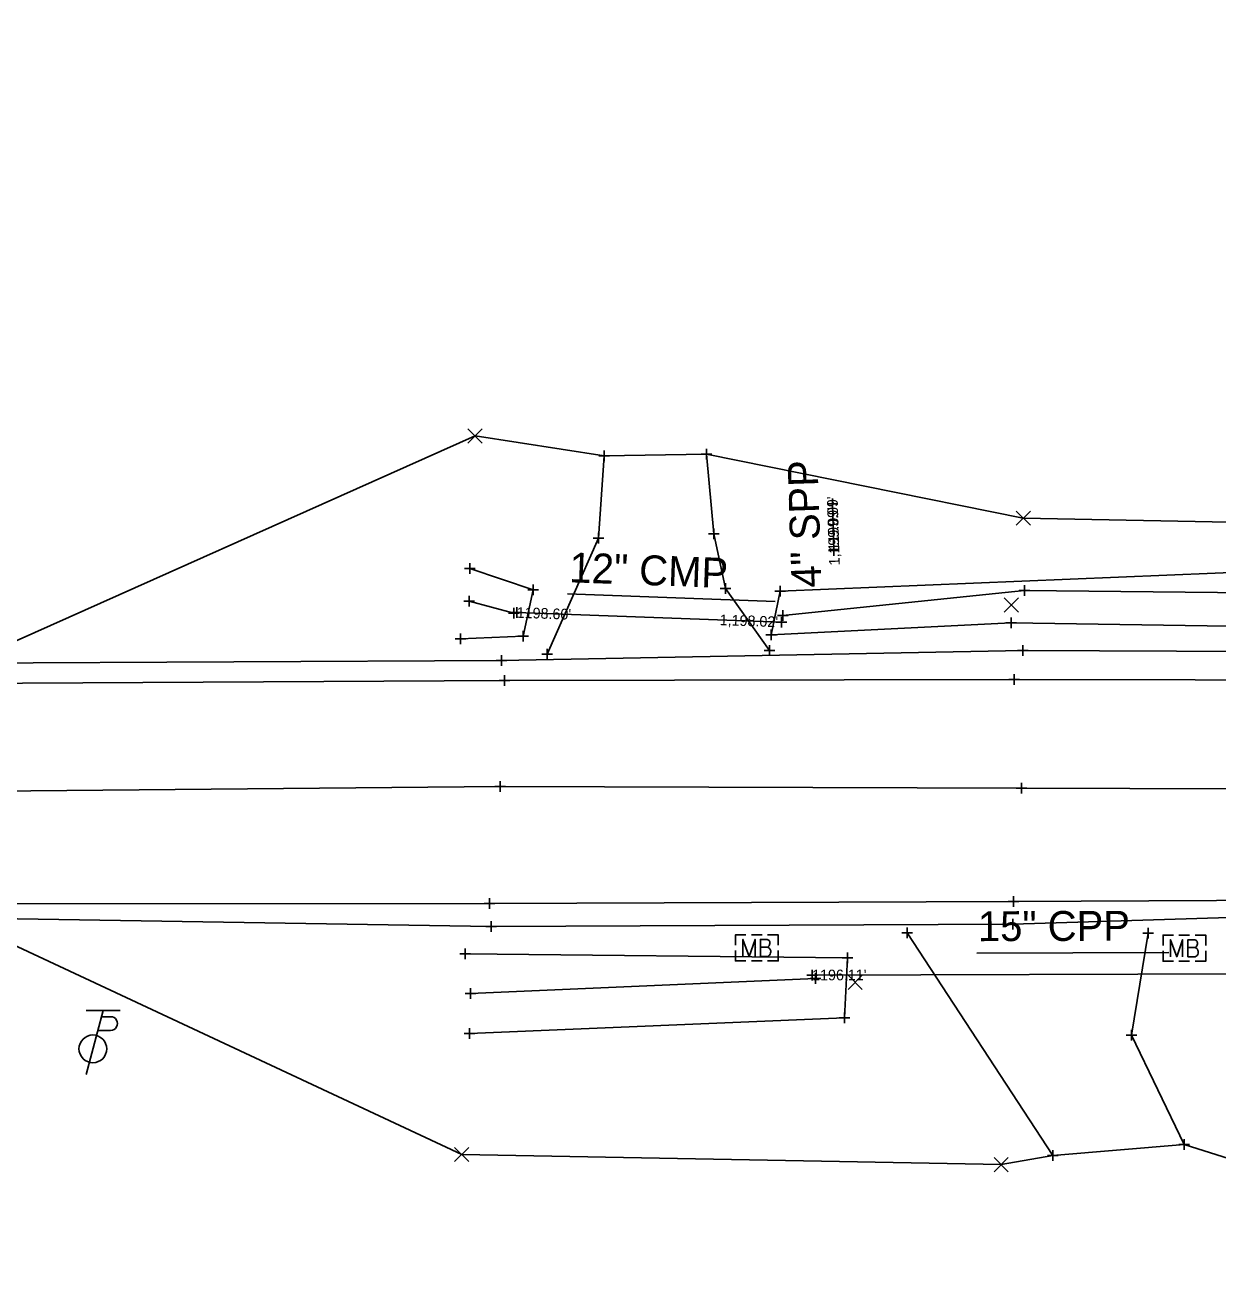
# Model space of a CAD drawing. Extents: x 2319153 to 2321514, y 575338 to 575500.
# Drawn here: x 2320371.3 to 2320483, y 575366.1 to 575483.2 of the extents above; entities that cross this region are included whole.
import ezdxf

# ---------------------------------------------------------------- set-up
doc = ezdxf.new("R2010")
doc.units = 0
for name, color, linetype in [('Default', 7, 'Continuous'), ('DR_X_Ditch', 7, 'Continuous'), ('DR_X_Elev_Flow', 7, 'Continuous'), ('DR_X_Storm_Sewer', 7, 'Continuous'), ('DR_X_Text', 7, 'Continuous'), ('PV_X_COP', 7, 'Continuous'), ('PV_X_Driveway', 7, 'Continuous'), ('PV_X_EOP', 7, 'Continuous'), ('PV_X_Shoulder', 7, 'Continuous'), ('RD_X_Cells', 7, 'Continuous'), ('SC_Scratch1', 7, 'Continuous'), ('SV_X_Break_Lines', 7, 'Continuous'), ('SV_X_Random_Point', 7, 'Continuous'), ('SV_X_Shot_Marker', 7, 'Continuous'), ('SV_X_Terrain_Boundary', 7, 'Continuous'), ('UT_X_Misc_Cells', 7, 'Continuous')]:
    doc.layers.add(name, color=color, linetype=linetype)

msp = doc.modelspace()

# ---------------------------------------------------------------- linework, layer by layer
at = {"layer": 'Default'}
msp.add_line((2320447.05, 575434.03), (2320447.05, 575434.03), dxfattribs=at)
at = {"layer": 'DR_X_Ditch'}
for points in [[(2320442.27, 575427.97), (2320464.89, 575430.3), (2320567.27, 575429.23), (2320616.67, 575430.56), (2320664.25, 575431.29), (2320715.69, 575433.03), (2320722.62, 575480.62)], [(2320417.08, 575428.19), (2320412.9, 575429.31)], [(2320445.33, 575393.97), (2320413.01, 575392.58)]]:
    msp.add_lwpolyline(points, dxfattribs=at)
at = {"layer": 'DR_X_Elev_Flow'}
for p, q in [((2320446.91, 575438.92), (2320446.91, 575437.92)), ((2320446.41, 575438.42), (2320447.41, 575438.42)), ((2320446.91, 575438.42), (2320446.91, 575438.42)), ((2320446.55, 575434.03), (2320447.55, 575434.03)), ((2320447.05, 575434.53), (2320447.05, 575433.53)), ((2320447.05, 575434.03), (2320447.05, 575434.03)), ((2320416.85, 575428.25), (2320417.85, 575428.25)), ((2320417.35, 575428.75), (2320417.35, 575427.75)), ((2320417.35, 575428.25), (2320417.35, 575428.25)), ((2320441.64, 575427.35), (2320442.64, 575427.35)), ((2320442.14, 575427.85), (2320442.14, 575426.85)), ((2320442.14, 575427.35), (2320442.14, 575427.35)), ((2320444.51, 575394.3), (2320445.51, 575394.3)), ((2320445.01, 575394.8), (2320445.01, 575393.8)), ((2320445.01, 575394.3), (2320445.01, 575394.3))]:
    msp.add_line(p, q, dxfattribs=at)
at = {"layer": 'DR_X_Storm_Sewer'}
for p, q in [((2320447.05, 575434.03), (2320446.91, 575438.42)), ((2320417.35, 575428.25), (2320442.14, 575427.35)), ((2320445.01, 575394.3), (2320489.84, 575394.42))]:
    msp.add_line(p, q, dxfattribs=at)
at = {"layer": 'DR_X_Text'}
for p, q in [((2320441.54, 575429.27), (2320422.09, 575429.98)), ((2320478.41, 575396.42), (2320460.43, 575396.36))]:
    msp.add_line(p, q, dxfattribs=at)
at = {"layer": 'PV_X_COP'}
msp.add_lwpolyline([(2320114.93, 575411.33), (2320165.7, 575411.06), (2320216.04, 575411.34), (2320265.84, 575411.19), (2320315.14, 575411.25), (2320365.04, 575411.47), (2320415.78, 575411.96), (2320464.61, 575411.79), (2320515.32, 575411.65), (2320564.75, 575412.16), (2320614.38, 575411.69), (2320664.58, 575411.98), (2320714.9, 575412.38)], dxfattribs=at)
at = {"layer": 'PV_X_Driveway'}
for points in [[(2320425.54, 575442.92), (2320425, 575435.21), (2320420.2, 575424.33)], [(2320441.02, 575424.67), (2320436.9, 575430.5), (2320435.81, 575435.6), (2320435.13, 575443.06)], [(2320467.54, 575377.42), (2320453.9, 575398.24)], [(2320476.49, 575398.21), (2320474.92, 575388.68), (2320479.84, 575378.43)]]:
    msp.add_lwpolyline(points, dxfattribs=at)
at = {"layer": 'PV_X_EOP'}
for points in [[(2320093.83, 575421.33), (2320165.53, 575421.34), (2320217.08, 575420.91), (2320266.56, 575421.33), (2320315.91, 575421.64), (2320365.38, 575421.59), (2320416.21, 575421.87), (2320463.92, 575421.98), (2320514.77, 575421.86), (2320565.11, 575422.28), (2320615.12, 575422), (2320664.7, 575422.48), (2320715.11, 575422.41)], [(2320714.4, 575401.87), (2320664.35, 575401.67), (2320614.5, 575401.81), (2320564.7, 575401.89), (2320514.59, 575401.42), (2320463.88, 575401.2), (2320414.8, 575400.99), (2320364.6, 575400.96), (2320315.2, 575400.77), (2320265.49, 575400.71), (2320215.68, 575400.77), (2320165.34, 575400.63), (2320115.4, 575400.66)]]:
    msp.add_lwpolyline(points, dxfattribs=at)
at = {"layer": 'PV_X_Shoulder'}
for points in [[(2320077.57, 575423.62), (2320166.34, 575422.88), (2320218.2, 575423.13), (2320266.92, 575423.62), (2320316.5, 575423.54), (2320365.74, 575423.49), (2320415.91, 575423.76), (2320464.74, 575424.68), (2320515.05, 575424.47), (2320565.23, 575424.51), (2320615.54, 575424.46), (2320664.52, 575424.33), (2320715.19, 575424.71)], [(2320714.58, 575400.4), (2320664.56, 575400.05), (2320614.84, 575400.09), (2320564.64, 575399.89), (2320515.49, 575400.65), (2320463.79, 575399.05), (2320414.96, 575398.83), (2320364.78, 575399.66), (2320315.61, 575399.52), (2320265.3, 575399.56), (2320215.74, 575399.78), (2320165.72, 575399.22), (2320115.8, 575398.99)]]:
    msp.add_lwpolyline(points, dxfattribs=at)
at = {"layer": 'RD_X_Cells'}
for p, q in [((2320439.32, 575398.06), (2320440.32, 575398.06)), ((2320479.36, 575398.04), (2320480.36, 575398.04)), ((2320439.83, 575396.84), (2320439.83, 575396.84)), ((2320479.87, 575396.81), (2320479.87, 575396.81)), ((2320439.32, 575395.62), (2320440.32, 575395.62)), ((2320479.36, 575395.59), (2320480.36, 575395.59))]:
    msp.add_line(p, q, dxfattribs=at)
for points in [[(2320437.83, 575397.09), (2320437.83, 575398.06), (2320438.8, 575398.06)], [(2320438.53, 575396.04), (2320438.53, 575397.64), (2320439.11, 575396.04), (2320439.67, 575397.64), (2320439.67, 575396.04)], [(2320440.85, 575396.91), (2320440.92, 575396.98), (2320440.95, 575397.01), (2320440.98, 575397.05), (2320440.99, 575397.08), (2320441.02, 575397.13), (2320441.03, 575397.16), (2320441.05, 575397.25), (2320441.05, 575397.29), (2320441.05, 575397.34), (2320441.04, 575397.42), (2320441.02, 575397.48), (2320440.98, 575397.53), (2320440.92, 575397.58), (2320440.87, 575397.61), (2320440.84, 575397.62), (2320440.78, 575397.64), (2320440.16, 575397.64), (2320440.16, 575396.04), (2320440.85, 575396.04), (2320440.94, 575396.09), (2320441.02, 575396.16), (2320441.08, 575396.26), (2320441.12, 575396.37), (2320441.13, 575396.48), (2320441.13, 575396.56), (2320441.1, 575396.64), (2320441.05, 575396.75), (2320440.99, 575396.82), (2320440.85, 575396.91), (2320440.16, 575396.91)], [(2320440.84, 575398.06), (2320441.83, 575398.06), (2320441.83, 575397.09)], [(2320477.87, 575397.07), (2320477.87, 575398.04), (2320478.84, 575398.04)], [(2320478.57, 575396.01), (2320478.57, 575397.61), (2320479.15, 575396.01), (2320479.71, 575397.61), (2320479.71, 575396.01)], [(2320480.89, 575396.88), (2320480.96, 575396.95), (2320480.99, 575396.98), (2320481.02, 575397.02), (2320481.03, 575397.05), (2320481.06, 575397.1), (2320481.07, 575397.14), (2320481.09, 575397.22), (2320481.09, 575397.26), (2320481.09, 575397.31), (2320481.08, 575397.39), (2320481.06, 575397.45), (2320481.02, 575397.5), (2320480.96, 575397.55), (2320480.91, 575397.58), (2320480.88, 575397.59), (2320480.82, 575397.61), (2320480.2, 575397.61), (2320480.2, 575396.01), (2320480.89, 575396.01), (2320480.98, 575396.06), (2320481.06, 575396.13), (2320481.12, 575396.23), (2320481.16, 575396.34), (2320481.17, 575396.45), (2320481.17, 575396.53), (2320481.14, 575396.61), (2320481.09, 575396.72), (2320481.03, 575396.79), (2320480.89, 575396.88), (2320480.2, 575396.88)], [(2320480.88, 575398.04), (2320481.87, 575398.04), (2320481.87, 575397.07)], [(2320438.8, 575395.62), (2320437.83, 575395.62), (2320437.83, 575396.59)], [(2320441.83, 575396.59), (2320441.83, 575395.62), (2320440.84, 575395.62)], [(2320478.84, 575395.59), (2320477.87, 575395.59), (2320477.87, 575396.56)], [(2320481.87, 575396.56), (2320481.87, 575395.59), (2320480.88, 575395.59)]]:
    msp.add_lwpolyline(points, dxfattribs=at)
at = {"layer": 'SV_X_Break_Lines'}
for points in [[(2320732.93, 575442.06), (2320727.34, 575431.55), (2320720.41, 575425.89), (2320664.7, 575425.9), (2320613.83, 575426.05), (2320563.12, 575426.93), (2320514.6, 575426.5), (2320463.64, 575427.26), (2320441.18, 575426.16), (2320442.02, 575430.24), (2320514.44, 575433.22), (2320564.58, 575433.19), (2320614.81, 575433.37), (2320685.2, 575436.83)], [(2320412.95, 575432.36), (2320418.87, 575430.36), (2320417.96, 575426.01), (2320412.07, 575425.78)], [(2320412.92, 575388.84), (2320448.04, 575390.29), (2320448.32, 575395.92), (2320412.51, 575396.28)]]:
    msp.add_lwpolyline(points, dxfattribs=at)
at = {"layer": 'SV_X_Random_Point'}
for p, q in [((2320412.78, 575444.1), (2320414.11, 575445.44)), ((2320412.78, 575445.44), (2320414.11, 575444.1)), ((2320464.11, 575436.41), (2320465.45, 575437.74)), ((2320464.11, 575437.74), (2320465.45, 575436.41)), ((2320463, 575428.27), (2320464.34, 575429.6)), ((2320463, 575429.6), (2320464.34, 575428.27)), ((2320448.37, 575392.95), (2320449.71, 575394.29)), ((2320448.37, 575394.29), (2320449.71, 575392.95)), ((2320411.52, 575376.83), (2320412.86, 575378.16)), ((2320411.52, 575378.16), (2320412.86, 575376.83)), ((2320462.05, 575375.88), (2320463.38, 575377.21)), ((2320462.05, 575377.21), (2320463.38, 575375.88))]:
    msp.add_line(p, q, dxfattribs=at)
at = {"layer": 'SV_X_Shot_Marker'}
for p, q in [((2320425.54, 575443.42), (2320425.54, 575442.42)), ((2320435.13, 575443.56), (2320435.13, 575442.56)), ((2320425.04, 575442.92), (2320426.04, 575442.92)), ((2320425.54, 575442.92), (2320425.54, 575442.92)), ((2320434.63, 575443.06), (2320435.63, 575443.06)), ((2320435.13, 575443.06), (2320435.13, 575443.06)), ((2320424.5, 575435.21), (2320425.5, 575435.21)), ((2320425, 575435.71), (2320425, 575434.71)), ((2320425, 575435.21), (2320425, 575435.21)), ((2320435.31, 575435.6), (2320436.31, 575435.6)), ((2320435.81, 575436.1), (2320435.81, 575435.1)), ((2320435.81, 575435.6), (2320435.81, 575435.6)), ((2320412.95, 575432.86), (2320412.95, 575431.86)), ((2320412.45, 575432.36), (2320413.45, 575432.36)), ((2320412.95, 575432.36), (2320412.95, 575432.36)), ((2320418.37, 575430.36), (2320419.37, 575430.36)), ((2320418.87, 575430.86), (2320418.87, 575429.86)), ((2320418.87, 575430.36), (2320418.87, 575430.36)), ((2320436.4, 575430.5), (2320437.4, 575430.5)), ((2320436.9, 575431), (2320436.9, 575430)), ((2320436.9, 575430.5), (2320436.9, 575430.5)), ((2320442.02, 575430.74), (2320442.02, 575429.74)), ((2320464.89, 575430.8), (2320464.89, 575429.8)), ((2320412.4, 575429.31), (2320413.4, 575429.31)), ((2320412.9, 575429.81), (2320412.9, 575428.81)), ((2320412.9, 575429.31), (2320412.9, 575429.31)), ((2320441.52, 575430.24), (2320442.52, 575430.24)), ((2320442.02, 575430.24), (2320442.02, 575430.24)), ((2320464.39, 575430.3), (2320465.39, 575430.3)), ((2320464.89, 575430.3), (2320464.89, 575430.3)), ((2320416.58, 575428.19), (2320417.58, 575428.19)), ((2320417.08, 575428.69), (2320417.08, 575427.69)), ((2320417.08, 575428.19), (2320417.08, 575428.19)), ((2320442.27, 575428.47), (2320442.27, 575427.47)), ((2320441.77, 575427.97), (2320442.77, 575427.97)), ((2320442.27, 575427.97), (2320442.27, 575427.97)), ((2320463.14, 575427.26), (2320464.14, 575427.26)), ((2320463.64, 575427.76), (2320463.64, 575426.76)), ((2320463.64, 575427.26), (2320463.64, 575427.26)), ((2320411.57, 575425.78), (2320412.57, 575425.78)), ((2320412.07, 575426.28), (2320412.07, 575425.28)), ((2320412.07, 575425.78), (2320412.07, 575425.78)), ((2320417.46, 575426.01), (2320418.46, 575426.01)), ((2320417.96, 575426.51), (2320417.96, 575425.51)), ((2320417.96, 575426.01), (2320417.96, 575426.01)), ((2320440.68, 575426.16), (2320441.68, 575426.16)), ((2320441.18, 575426.66), (2320441.18, 575425.66)), ((2320441.18, 575426.16), (2320441.18, 575426.16)), ((2320420.2, 575424.83), (2320420.2, 575423.83)), ((2320440.52, 575424.67), (2320441.52, 575424.67)), ((2320441.02, 575425.17), (2320441.02, 575424.17)), ((2320441.02, 575424.67), (2320441.02, 575424.67)), ((2320464.24, 575424.68), (2320465.24, 575424.68)), ((2320464.74, 575425.18), (2320464.74, 575424.18)), ((2320464.74, 575424.68), (2320464.74, 575424.68)), ((2320415.41, 575423.76), (2320416.41, 575423.76)), ((2320415.91, 575424.26), (2320415.91, 575423.26)), ((2320415.91, 575423.76), (2320415.91, 575423.76)), ((2320419.7, 575424.33), (2320420.7, 575424.33)), ((2320420.2, 575424.33), (2320420.2, 575424.33)), ((2320416.21, 575422.37), (2320416.21, 575421.37)), ((2320463.92, 575422.48), (2320463.92, 575421.48)), ((2320415.71, 575421.87), (2320416.71, 575421.87)), ((2320416.21, 575421.87), (2320416.21, 575421.87)), ((2320463.42, 575421.98), (2320464.42, 575421.98)), ((2320463.92, 575421.98), (2320463.92, 575421.98)), ((2320415.28, 575411.96), (2320416.28, 575411.96)), ((2320415.78, 575412.46), (2320415.78, 575411.46)), ((2320415.78, 575411.96), (2320415.78, 575411.96)), ((2320464.11, 575411.79), (2320465.11, 575411.79)), ((2320464.61, 575412.29), (2320464.61, 575411.29)), ((2320464.61, 575411.79), (2320464.61, 575411.79)), ((2320414.8, 575401.49), (2320414.8, 575400.49)), ((2320463.38, 575401.2), (2320464.38, 575401.2)), ((2320463.88, 575401.7), (2320463.88, 575400.7)), ((2320463.88, 575401.2), (2320463.88, 575401.2)), ((2320414.3, 575400.99), (2320415.3, 575400.99)), ((2320414.8, 575400.99), (2320414.8, 575400.99)), ((2320414.46, 575398.83), (2320415.46, 575398.83)), ((2320414.96, 575399.33), (2320414.96, 575398.33)), ((2320414.96, 575398.83), (2320414.96, 575398.83)), ((2320453.9, 575398.74), (2320453.9, 575397.74)), ((2320463.29, 575399.05), (2320464.29, 575399.05)), ((2320463.79, 575399.55), (2320463.79, 575398.55)), ((2320463.79, 575399.05), (2320463.79, 575399.05)), ((2320453.4, 575398.24), (2320454.4, 575398.24)), ((2320453.9, 575398.24), (2320453.9, 575398.24)), ((2320475.99, 575398.21), (2320476.99, 575398.21)), ((2320476.49, 575398.71), (2320476.49, 575397.71)), ((2320476.49, 575398.21), (2320476.49, 575398.21)), ((2320412.51, 575396.78), (2320412.51, 575395.78)), ((2320448.32, 575396.42), (2320448.32, 575395.42)), ((2320412.01, 575396.28), (2320413.01, 575396.28)), ((2320412.51, 575396.28), (2320412.51, 575396.28)), ((2320447.82, 575395.92), (2320448.82, 575395.92)), ((2320448.32, 575395.92), (2320448.32, 575395.92)), ((2320445.33, 575394.47), (2320445.33, 575393.47)), ((2320413.01, 575393.08), (2320413.01, 575392.08)), ((2320444.83, 575393.97), (2320445.83, 575393.97)), ((2320445.33, 575393.97), (2320445.33, 575393.97)), ((2320412.51, 575392.58), (2320413.51, 575392.58)), ((2320413.01, 575392.58), (2320413.01, 575392.58)), ((2320448.04, 575390.79), (2320448.04, 575389.79)), ((2320447.54, 575390.29), (2320448.54, 575390.29)), ((2320448.04, 575390.29), (2320448.04, 575390.29)), ((2320412.42, 575388.84), (2320413.42, 575388.84)), ((2320412.92, 575389.34), (2320412.92, 575388.34)), ((2320412.92, 575388.84), (2320412.92, 575388.84)), ((2320474.42, 575388.68), (2320475.42, 575388.68)), ((2320474.92, 575389.18), (2320474.92, 575388.18)), ((2320474.92, 575388.68), (2320474.92, 575388.68)), ((2320479.84, 575378.93), (2320479.84, 575377.93)), ((2320467.54, 575377.92), (2320467.54, 575376.92)), ((2320479.34, 575378.43), (2320480.34, 575378.43)), ((2320479.84, 575378.43), (2320479.84, 575378.43)), ((2320467.04, 575377.42), (2320468.04, 575377.42)), ((2320467.54, 575377.42), (2320467.54, 575377.42))]:
    msp.add_line(p, q, dxfattribs=at)
at = {"layer": 'SV_X_Terrain_Boundary'}
for points in [[(2320707.74, 575483.24), (2320663.9, 575465.47), (2320613.22, 575460.31), (2320572.01, 575459.01), (2320513.06, 575436.13), (2320464.78, 575437.07), (2320435.13, 575443.06), (2320425.54, 575442.92), (2320413.45, 575444.77), (2320365.74, 575423.49), (2320316.5, 575423.54), (2320266.92, 575423.62), (2320218.2, 575423.13), (2320166.34, 575422.88), (2320077.57, 575423.62)], [(2320077.57, 575423.62), (2320093.83, 575421.33), (2320114.93, 575411.33), (2320115.4, 575400.66), (2320115.8, 575398.99), (2320165.72, 575399.22), (2320215.74, 575399.78), (2320265.3, 575399.56), (2320315.61, 575399.52), (2320364.78, 575399.66), (2320412.19, 575377.5), (2320462.72, 575376.55), (2320467.54, 575377.42), (2320479.84, 575378.43), (2320488.25, 575375.78), (2320513.78, 575375.33), (2320556.07, 575376.66), (2320613.57, 575378.25), (2320654.2, 575376.01), (2320714.52, 575366.13)]]:
    msp.add_lwpolyline(points, dxfattribs=at)
at = {"layer": 'UT_X_Misc_Cells'}
for p, q in [((2320380.21, 575390.99), (2320377.01, 575390.99)), ((2320378.61, 575390.99), (2320377.01, 575384.99)), ((2320378.45, 575390.39), (2320379.3, 575390.39)), ((2320378.11, 575389.12), (2320379.3, 575389.12))]:
    msp.add_line(p, q, dxfattribs=at)
msp.add_circle((2320377.65, 575387.39), 1.3, dxfattribs=at)
msp.add_arc((2320379.32, 575389.76), 0.638, 268.8767, 91.1233, dxfattribs=at)

# ---------------------------------------------------------------- texts
at = {"layer": 'DR_X_Text'}
for s, rotation, p in [('4" SPP', 91.8276, (2320445.89, 575430.61)), ('12" CMP', 357.9216, (2320422.24, 575431.07)), ('15" CPP', 0.1614, (2320460.54, 575397.47))]:
    msp.add_text(s, height=2.8, rotation=rotation, dxfattribs=at).set_placement(p)
at = {"layer": 'SC_Scratch1'}
for s, rotation, p in [("1199.09'", 91.8276, (2320447.55, 575434.04)), ("1,199.09'", 91.8276, (2320447.6, 575432.66)), ("1198.60'", 357.9216, (2320417.33, 575427.75)), ("1,198.02'", 357.9216, (2320436.34, 575427.06)), ("1196.11'", 0.1614, (2320445.01, 575393.8))]:
    msp.add_text(s, height=1, rotation=rotation, dxfattribs=at).set_placement(p)

doc.saveas('drawing.dxf')
